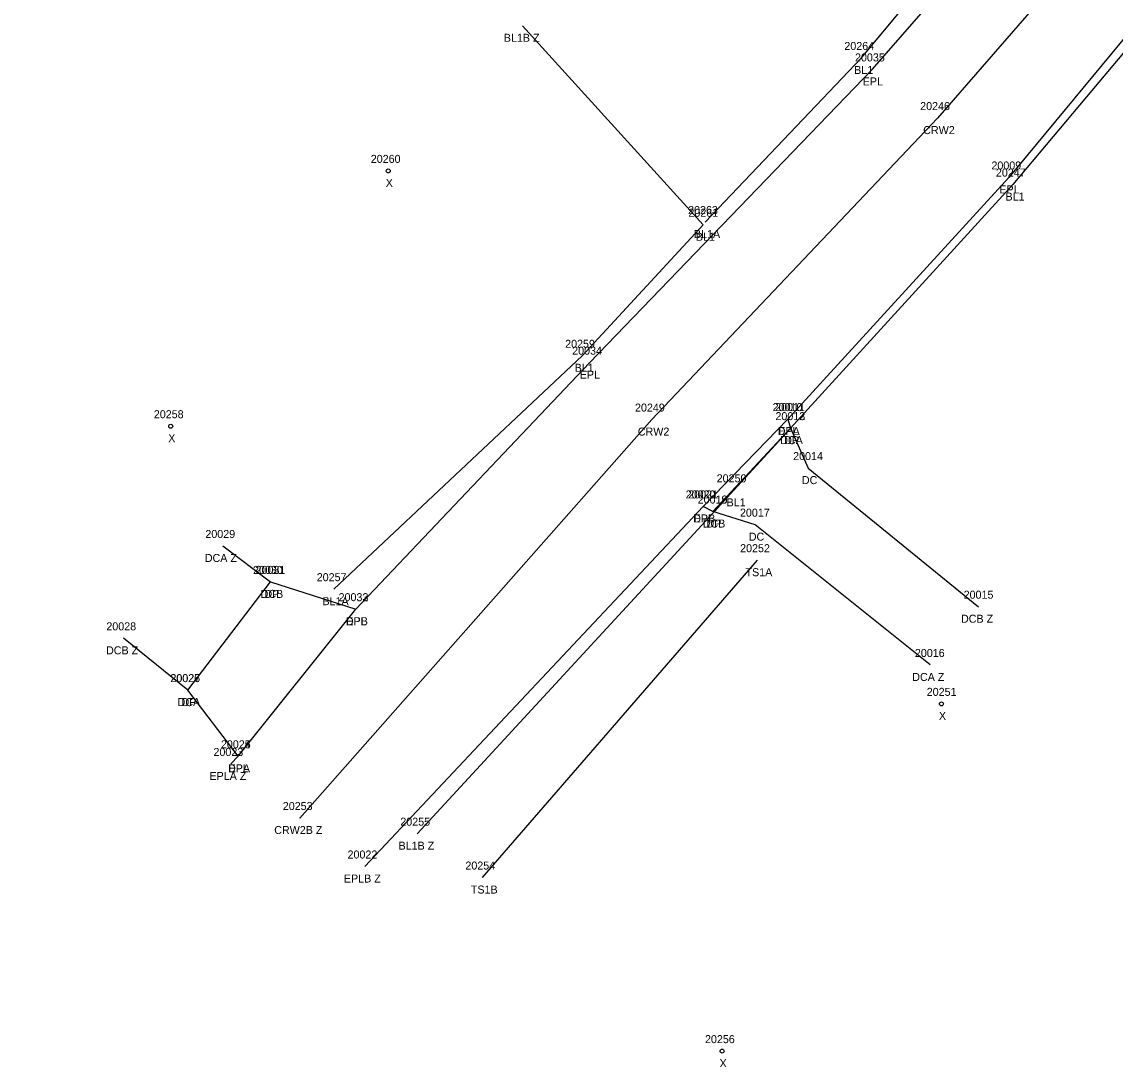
# Model space of a CAD drawing. Extents: x 1813127 to 1814107, y 1178171 to 1179078.
# Drawn here: x 1813803.8 to 1813940.4, y 1178170.7 to 1178301.3 of the extents above; entities that cross this region are included whole.
import ezdxf

# ---------------------------------------------------------------- set-up
doc = ezdxf.new("R2010")
doc.units = 0
for name, color, linetype in [('RD_DTM_BkLn1', 7, 'Continuous'), ('RD_DTM_BkLn2', 7, 'Continuous'), ('RD_EX_Conc', 7, 'Continuous'), ('RD_EX_Conc_txCode', 7, 'Continuous'), ('RD_EX_Driveway', 7, 'Continuous'), ('RD_EX_Driveway_txCode', 7, 'Continuous'), ('RD_EX_Road', 7, 'Continuous'), ('RD_EX_Road_txCode', 7, 'Continuous'), ('RD_SMD_Locator', 7, 'Continuous'), ('RD_SMD_Misc', 7, 'Continuous')]:
    doc.layers.add(name, color=color, linetype=linetype)

msp = doc.modelspace()

# ---------------------------------------------------------------- linework, layer by layer
at = {"layer": 'RD_DTM_BkLn1'}
for points in [[(1814043.03, 1178443.95), (1814035.88, 1178434.61), (1814028.35, 1178424.67), (1814012.24, 1178403.85), (1813982.68, 1178367.11), (1813951.35, 1178327.47), (1813918.15, 1178289.3), (1813882.49, 1178251.63), (1813838.5, 1178201.85)], [(1813889.15, 1178276.31), (1813908.67, 1178296.81), (1813972.77, 1178373.79), (1814000.42, 1178410.19)], [(1814050.19, 1178394.52), (1814043.23, 1178402.26), (1814030.04, 1178381.54), (1813999.13, 1178354.11), (1813960.69, 1178320.44), (1813927.58, 1178280.99), (1813899.82, 1178250.55)], [(1813842.74, 1178230.44), (1813873.77, 1178259.6), (1813888.9, 1178275.97), (1813866.33, 1178300.83)], [(1813899.79, 1178250.52), (1813892.74, 1178242.79), (1813890.29, 1178240.13)], [(1813890.2, 1178240.04), (1813853.18, 1178199.89)]]:
    msp.add_lwpolyline(points, dxfattribs=at)
at = {"layer": 'RD_DTM_BkLn2'}
msp.add_line((1813895.63, 1178234.06), (1813861.3, 1178194.41), dxfattribs=at)
at = {"layer": 'RD_EX_Conc'}
for p, q in [((1813828.87, 1178235.84), (1813834.86, 1178231.35)), ((1813824.51, 1178217.83), (1813816.5, 1178224.3))]:
    msp.add_line(p, q, dxfattribs=at)
for points in [[(1813899.79, 1178250.56), (1813902, 1178245.57), (1813923.3, 1178228.25)], [(1813917.24, 1178220.97), (1813895.37, 1178238.5), (1813890.08, 1178240.14)]]:
    msp.add_lwpolyline(points, dxfattribs=at)
at = {"layer": 'RD_EX_Driveway'}
for points in [[(1813899.48, 1178251.69), (1813899.79, 1178250.56), (1813890.08, 1178240.14), (1813888.9, 1178240.78)], [(1813830.81, 1178209.56), (1813824.51, 1178217.83), (1813834.86, 1178231.35), (1813845.51, 1178227.94)]]:
    msp.add_lwpolyline(points, dxfattribs=at)
at = {"layer": 'RD_EX_Road'}
for points in [[(1813829.87, 1178208.6), (1813830.81, 1178209.56), (1813845.51, 1178227.94), (1813874.69, 1178258.74), (1813910.02, 1178295.38), (1813943.63, 1178333.84), (1813974.31, 1178373.09), (1814001.91, 1178410.56), (1814011.9, 1178425.95), (1814015.58, 1178434.3), (1814016.71, 1178442.08), (1814017.03, 1178447.13), (1814015.19, 1178453.67), (1813986.47, 1178480.85), (1813949.15, 1178515.86), (1813911.94, 1178551.77), (1813875.67, 1178586.1), (1813838.32, 1178620.7), (1813831.51, 1178622), (1813823.35, 1178621.08), (1813815.99, 1178618.51), (1813795.14, 1178605.39)], [(1814062.16, 1178410.76), (1814056.57, 1178415.98), (1814052.15, 1178418.06), (1814044.5, 1178417.46), (1814039.53, 1178416.2), (1814027.18, 1178402.17), (1814022.8, 1178396.98), (1813991.69, 1178360.57), (1813959.64, 1178321.24), (1813927.09, 1178281.88), (1813899.48, 1178251.69), (1813888.9, 1178240.78), (1813846.63, 1178195.79)]]:
    msp.add_lwpolyline(points, dxfattribs=at)
at = {"layer": 'RD_SMD_Locator'}
for centre, radius in [((1813866.33, 1178300.83), 0.001), ((1813908.67, 1178296.81), 0.001), ((1813910.02, 1178295.38), 0.001), ((1813918.15, 1178289.3), 0.001), ((1813849.55, 1178282.7), 0.25), ((1813927.09, 1178281.88), 0.001), ((1813927.58, 1178280.99), 0.001), ((1813889.15, 1178276.31), 0.001), ((1813888.9, 1178275.97), 0.001), ((1813873.77, 1178259.6), 0.001), ((1813874.69, 1178258.74), 0.001), ((1813882.49, 1178251.63), 0.001), ((1813899.48, 1178251.69), 0.001), ((1813899.48, 1178251.69), 0.001), ((1813822.38, 1178250.8), 0.25), ((1813899.79, 1178250.56), 0.001), ((1813899.79, 1178250.56), 0.001), ((1813902, 1178245.57), 0.001), ((1813892.74, 1178242.79), 0.001), ((1813888.9, 1178240.78), 0.001), ((1813888.9, 1178240.78), 0.001), ((1813890.08, 1178240.14), 0.001), ((1813890.08, 1178240.14), 0.001), ((1813895.37, 1178238.5), 0.001), ((1813828.87, 1178235.84), 0.001), ((1813895.63, 1178234.06), 0.001), ((1813834.86, 1178231.35), 0.001), ((1813834.86, 1178231.35), 0.001), ((1813842.74, 1178230.44), 0.001), ((1813845.51, 1178227.94), 0.001), ((1813845.51, 1178227.94), 0.001), ((1813923.3, 1178228.25), 0.001), ((1813816.5, 1178224.3), 0.001), ((1813917.24, 1178220.97), 0.001), ((1813824.51, 1178217.83), 0.001), ((1813824.51, 1178217.83), 0.001), ((1813918.66, 1178216.11), 0.25), ((1813830.81, 1178209.56), 0.001), ((1813830.81, 1178209.56), 0.001), ((1813829.87, 1178208.6), 0.001), ((1813838.5, 1178201.85), 0.001), ((1813853.18, 1178199.89), 0.001), ((1813846.63, 1178195.79), 0.001), ((1813861.3, 1178194.41), 0.001), ((1813891.26, 1178172.72), 0.25)]:
    msp.add_circle(centre, radius, dxfattribs=at)

# ---------------------------------------------------------------- texts
at = {"layer": 'RD_EX_Conc_txCode'}
for s, p in [('20013', (1813897.92, 1178251.56)), ('DCA', (1813898.52, 1178248.56)), ('20014', (1813900.13, 1178246.57)), ('DC', (1813901.22, 1178243.57)), ('20018', (1813888.21, 1178241.14)), ('20017', (1813893.49, 1178239.5)), ('20029', (1813826.71, 1178236.84)), ('DCB', (1813888.83, 1178238.14)), ('DC', (1813894.59, 1178236.5)), ('DCA Z', (1813826.64, 1178233.84)), ('20030', (1813832.66, 1178232.35)), ('DCB', (1813833.61, 1178229.35)), ('20015', (1813921.43, 1178229.25)), ('DCB Z', (1813921.1, 1178226.25)), ('20028', (1813814.34, 1178225.3)), ('DCB Z', (1813814.3, 1178222.3)), ('20016', (1813915.34, 1178221.97)), ('20027', (1813822.35, 1178218.83)), ('DCA Z', (1813915.01, 1178218.97)), ('DCA', (1813823.24, 1178215.83))]:
    msp.add_text(s, height=1, dxfattribs=at).set_placement(p)
at = {"layer": 'RD_EX_Driveway_txCode'}
for s, p in [('20011', (1813897.89, 1178252.69)), ('20012', (1813897.92, 1178251.56)), ('DPA', (1813898.21, 1178249.69)), ('DP', (1813899.01, 1178248.56)), ('20020', (1813886.71, 1178241.78)), ('20019', (1813888.21, 1178241.14)), ('DPB', (1813887.65, 1178238.78)), ('DP', (1813889.3, 1178238.14)), ('20031', (1813832.98, 1178232.35)), ('DP', (1813834.08, 1178229.35)), ('20032', (1813843.35, 1178228.94)), ('DPB', (1813844.26, 1178225.94)), ('20026', (1813822.33, 1178218.83)), ('DP', (1813823.73, 1178215.83)), ('20025', (1813828.65, 1178210.56)), ('DPA', (1813829.54, 1178207.56))]:
    msp.add_text(s, height=1, dxfattribs=at).set_placement(p)
at = {"layer": 'RD_EX_Road_txCode'}
for s, p in [('20035', (1813907.86, 1178296.38)), ('EPL', (1813908.82, 1178293.38)), ('20009', (1813924.9, 1178282.88)), ('EPL', (1813925.89, 1178279.88)), ('20034', (1813872.53, 1178259.74)), ('EPL', (1813873.48, 1178256.74)), ('20010', (1813897.57, 1178252.69)), ('EPL', (1813898.28, 1178249.69)), ('20021', (1813887.03, 1178241.78)), ('EPL', (1813887.7, 1178238.78)), ('20033', (1813843.35, 1178228.94)), ('EPL', (1813844.3, 1178225.94)), ('20023', (1813827.72, 1178209.6)), ('20024', (1813828.65, 1178210.56)), ('EPL', (1813829.6, 1178207.56)), ('EPLA Z', (1813827.22, 1178206.6)), ('20022', (1813844.47, 1178196.79)), ('EPLB Z', (1813844.01, 1178193.79))]:
    msp.add_text(s, height=1, dxfattribs=at).set_placement(p)
at = {"layer": 'RD_SMD_Misc'}
for s, p in [('BL1B Z', (1813863.99, 1178298.83)), ('20264', (1813906.53, 1178297.81)), ('BL1', (1813907.75, 1178294.81)), ('20246', (1813916, 1178290.3)), ('CRW2', (1813916.38, 1178287.3)), ('20260', (1813847.37, 1178283.7)), ('20247', (1813925.46, 1178281.99)), ('X', (1813849.24, 1178280.7)), ('BL1', (1813926.66, 1178278.99)), ('20263', (1813887.01, 1178277.31)), ('20261', (1813887.05, 1178276.97)), ('BL1A', (1813887.74, 1178274.31)), ('BL1', (1813887.98, 1178273.97)), ('20259', (1813871.65, 1178260.6)), ('BL1', (1813872.84, 1178257.6)), ('20249', (1813880.38, 1178252.63)), ('20258', (1813820.27, 1178251.8)), ('CRW2', (1813880.73, 1178249.63)), ('X', (1813822.07, 1178248.8)), ('20250', (1813890.58, 1178243.79)), ('BL1', (1813891.82, 1178240.79)), ('20252', (1813893.51, 1178235.06)), ('20257', (1813840.62, 1178231.44)), ('TS1A', (1813894.18, 1178232.06)), ('BL1A', (1813841.33, 1178228.44)), ('20251', (1813916.82, 1178217.11)), ('X', (1813918.34, 1178214.11)), ('20253', (1813836.38, 1178202.85)), ('20255', (1813851.06, 1178200.89)), ('CRW2B Z', (1813835.31, 1178199.85)), ('BL1B Z', (1813850.84, 1178197.89)), ('20254', (1813859.19, 1178195.41)), ('TS1B', (1813859.87, 1178192.41)), ('20256', (1813889.12, 1178173.72)), ('X', (1813890.94, 1178170.72))]:
    msp.add_text(s, height=1, dxfattribs=at).set_placement(p)

doc.saveas('drawing.dxf')
